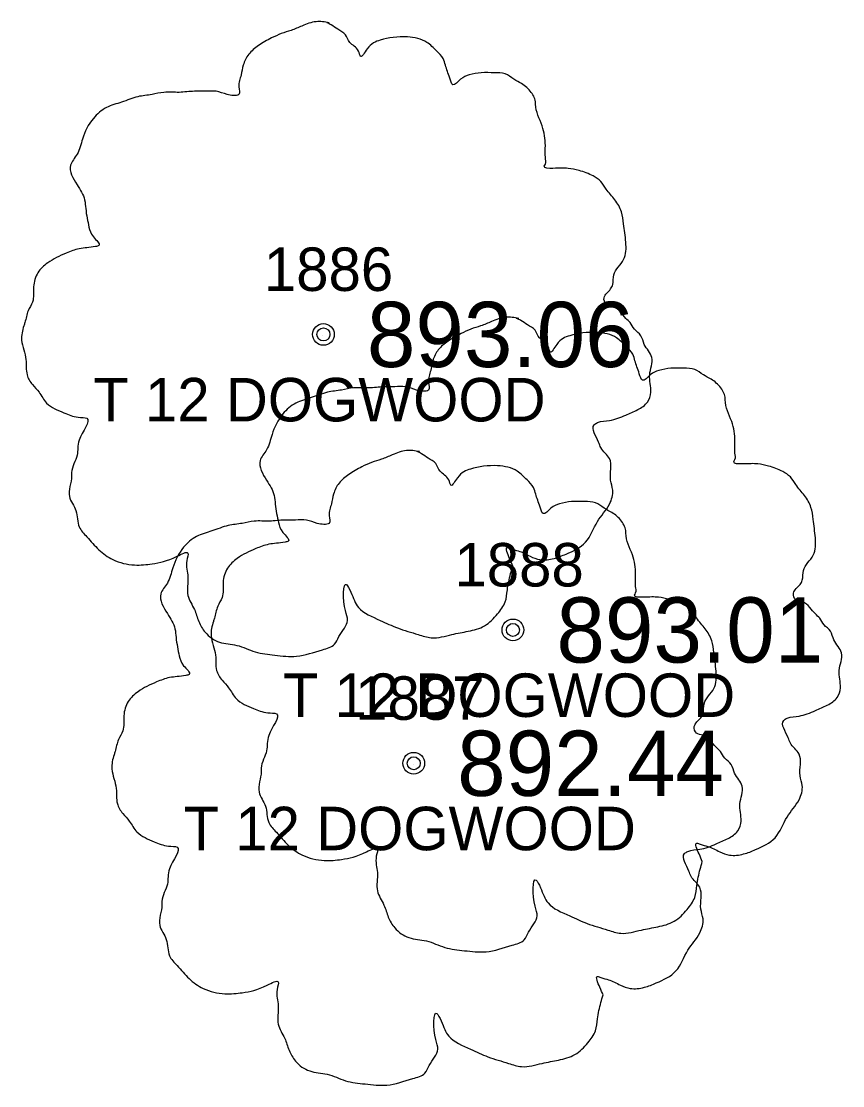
# Model space of a CAD drawing. Extents: x 1448136 to 1453623, y 1125056 to 1128842.
# Drawn here: x 1449655.54 to 1449674.44, y 1126828.42 to 1126852.9 of the extents above; entities that cross this region are included whole.
import ezdxf

# ---------------------------------------------------------------- set-up
doc = ezdxf.new("R2010")
doc.units = 0
for name, color, linetype in [('RD_EX_TX_VEG_ELEV', 7, 'Continuous'), ('RD_EX_VEG', 7, 'Continuous'), ('RD_EX_VEG_txCode', 7, 'Continuous'), ('RD_SMD_Locator', 7, 'Continuous')]:
    doc.layers.add(name, color=color, linetype=linetype)

msp = doc.modelspace()

# ---------------------------------------------------------------- linework, layer by layer
at = {"layer": 'RD_EX_VEG'}
for centre, radius in [((1449662.493, 1126845.694), 0.25), ((1449662.48, 1126845.675), 0.0001), ((1449666.852, 1126838.897), 0.25), ((1449666.839, 1126838.878), 0.0001), ((1449664.569, 1126835.831), 0.25), ((1449664.557, 1126835.812), 0.0001)]:
    msp.add_circle(centre, radius, dxfattribs=at)
for points in [[(1449662.625, 1126852.862), (1449662.325, 1126852.887), (1449662, 1126852.787), (1449661.75, 1126852.687), (1449661.525, 1126852.612), (1449661.3, 1126852.512), (1449661, 1126852.337), (1449660.775, 1126852.137), (1449660.65, 1126851.887), (1449660.6, 1126851.662), (1449660.551, 1126851.387), (1449660.551, 1126851.212), (1449660.426, 1126851.187), (1449660.276, 1126851.212), (1449660.026, 1126851.287), (1449659.776, 1126851.287), (1449659.526, 1126851.287), (1449659.176, 1126851.262), (1449658.826, 1126851.262), (1449658.551, 1126851.212), (1449658.227, 1126851.162), (1449657.852, 1126851.037), (1449657.502, 1126850.912), (1449657.202, 1126850.662), (1449656.952, 1126850.188), (1449656.827, 1126849.838), (1449656.677, 1126849.588), (1449656.827, 1126849.138), (1449657.002, 1126848.788), (1449657.027, 1126848.588), (1449657.102, 1126848.164), (1449657.202, 1126847.939), (1449657.327, 1126847.739), (1449657.252, 1126847.714), (1449656.877, 1126847.664), (1449656.577, 1126847.564), (1449656.152, 1126847.339), (1449655.928, 1126847.114), (1449655.828, 1126846.789), (1449655.803, 1126846.439), (1449655.703, 1126846.239), (1449655.628, 1126845.965), (1449655.603, 1126845.89), (1449655.553, 1126845.565), (1449655.653, 1126845.115), (1449655.678, 1126844.765), (1449655.803, 1126844.54), (1449655.953, 1126844.365), (1449656.127, 1126844.115), (1449656.527, 1126843.89), (1449656.852, 1126843.79), (1449657.052, 1126843.766), (1449656.877, 1126843.266), (1449656.827, 1126842.916), (1449656.702, 1126842.516), (1449656.702, 1126842.441), (1449656.652, 1126841.966), (1449656.802, 1126841.641), (1449656.877, 1126841.267), (1449657.052, 1126841.042), (1449657.327, 1126840.742), (1449657.652, 1126840.517), (1449658.152, 1126840.392), (1449658.551, 1126840.417), (1449659.126, 1126840.592), (1449659.376, 1126840.667), (1449659.351, 1126840.492), (1449659.376, 1126840.117), (1449659.376, 1126839.692), (1449659.526, 1126839.367), (1449659.626, 1126839.093), (1449659.776, 1126838.843), (1449660.101, 1126838.618), (1449660.501, 1126838.543), (1449660.925, 1126838.393), (1449661.375, 1126838.318), (1449661.875, 1126838.293), (1449662.475, 1126838.443), (1449662.75, 1126838.568), (1449662.85, 1126838.743), (1449663.049, 1126839.118), (1449662.999, 1126839.342), (1449663.024, 1126839.942), (1449663.124, 1126839.767), (1449663.299, 1126839.417), (1449663.799, 1126839.118), (1449664.199, 1126838.943), (1449664.674, 1126838.793), (1449664.974, 1126838.718), (1449665.448, 1126838.793), (1449665.823, 1126838.868), (1449666.198, 1126838.993), (1449666.498, 1126839.267), (1449666.673, 1126839.542), (1449666.723, 1126839.817), (1449666.798, 1126840.192), (1449666.848, 1126840.367)], [(1449666.848, 1126840.367), (1449666.773, 1126840.542), (1449666.723, 1126840.792), (1449666.798, 1126840.767), (1449666.973, 1126840.717), (1449667.248, 1126840.592), (1449667.473, 1126840.517), (1449667.797, 1126840.542), (1449668.072, 1126840.642), (1449668.522, 1126840.917), (1449668.797, 1126841.392), (1449669.072, 1126841.791), (1449669.147, 1126842.116), (1449669.097, 1126842.341), (1449669.072, 1126842.841), (1449668.872, 1126843.091), (1449668.822, 1126843.216), (1449668.722, 1126843.616), (1449668.797, 1126843.666), (1449669.072, 1126843.716), (1449669.447, 1126843.84), (1449669.722, 1126843.965), (1449669.946, 1126844.14), (1449670.021, 1126844.365), (1449669.996, 1126844.765), (1449670.046, 1126845.165), (1449669.971, 1126845.315), (1449669.871, 1126845.465), (1449669.796, 1126845.665), (1449669.647, 1126845.815), (1449669.547, 1126845.965), (1449669.447, 1126846.064), (1449669.322, 1126846.214), (1449669.147, 1126846.339), (1449668.997, 1126846.389), (1449668.947, 1126846.539), (1449669.097, 1126846.739), (1449669.147, 1126846.839), (1449669.172, 1126847.064), (1449669.397, 1126847.414), (1449669.447, 1126847.814), (1449669.397, 1126848.239), (1449669.347, 1126848.513), (1449669.197, 1126848.788), (1449668.997, 1126849.038), (1449668.872, 1126849.213), (1449668.697, 1126849.338), (1449668.372, 1126849.463), (1449668.122, 1126849.513), (1449667.772, 1126849.513), (1449667.572, 1126849.563), (1449667.597, 1126849.613), (1449667.597, 1126849.763), (1449667.597, 1126850.038), (1449667.522, 1126850.488), (1449667.373, 1126850.987), (1449667.373, 1126851.012), (1449667.273, 1126851.262), (1449667.048, 1126851.462), (1449666.873, 1126851.562), (1449666.673, 1126851.687), (1449666.423, 1126851.712), (1449666.123, 1126851.712), (1449665.848, 1126851.662), (1449665.648, 1126851.562), (1449665.473, 1126851.437), (1449665.398, 1126851.587), (1449665.298, 1126851.887), (1449665.248, 1126852.037), (1449665.099, 1126852.212), (1449664.874, 1126852.412), (1449664.424, 1126852.537), (1449663.799, 1126852.462), (1449663.499, 1126852.262), (1449663.349, 1126852.087), (1449663.299, 1126852.212), (1449663.099, 1126852.412), (1449662.999, 1126852.587), (1449662.825, 1126852.712), (1449662.675, 1126852.812), (1449662.575, 1126852.862)], [(1449666.984, 1126846.064), (1449666.684, 1126846.089), (1449666.359, 1126845.989), (1449666.109, 1126845.89), (1449665.884, 1126845.815), (1449665.66, 1126845.715), (1449665.36, 1126845.54), (1449665.135, 1126845.34), (1449665.01, 1126845.09), (1449664.96, 1126844.865), (1449664.91, 1126844.59), (1449664.91, 1126844.415), (1449664.785, 1126844.39), (1449664.635, 1126844.415), (1449664.385, 1126844.49), (1449664.135, 1126844.49), (1449663.885, 1126844.49), (1449663.535, 1126844.465), (1449663.186, 1126844.465), (1449662.911, 1126844.415), (1449662.586, 1126844.365), (1449662.211, 1126844.24), (1449661.861, 1126844.115), (1449661.561, 1126843.865), (1449661.311, 1126843.391), (1449661.186, 1126843.041), (1449661.037, 1126842.791), (1449661.186, 1126842.341), (1449661.361, 1126841.991), (1449661.386, 1126841.791), (1449661.461, 1126841.367), (1449661.561, 1126841.142), (1449661.686, 1126840.942), (1449661.611, 1126840.917), (1449661.236, 1126840.867), (1449660.937, 1126840.767), (1449660.512, 1126840.542), (1449660.287, 1126840.317), (1449660.187, 1126839.992), (1449660.162, 1126839.642), (1449660.062, 1126839.442), (1449659.987, 1126839.167), (1449659.962, 1126839.092), (1449659.912, 1126838.768), (1449660.012, 1126838.318), (1449660.037, 1126837.968), (1449660.162, 1126837.743), (1449660.312, 1126837.568), (1449660.487, 1126837.318), (1449660.887, 1126837.093), (1449661.211, 1126836.993), (1449661.411, 1126836.968), (1449661.236, 1126836.469), (1449661.186, 1126836.119), (1449661.062, 1126835.719), (1449661.062, 1126835.644), (1449661.012, 1126835.169), (1449661.161, 1126834.844), (1449661.236, 1126834.47), (1449661.411, 1126834.245), (1449661.686, 1126833.945), (1449662.011, 1126833.72), (1449662.511, 1126833.595), (1449662.911, 1126833.62), (1449663.486, 1126833.795), (1449663.735, 1126833.87), (1449663.71, 1126833.695), (1449663.735, 1126833.32), (1449663.735, 1126832.895), (1449663.885, 1126832.57), (1449663.985, 1126832.295), (1449664.135, 1126832.046), (1449664.46, 1126831.821), (1449664.86, 1126831.746), (1449665.285, 1126831.596), (1449665.735, 1126831.521), (1449666.234, 1126831.496), (1449666.834, 1126831.646), (1449667.109, 1126831.771), (1449667.209, 1126831.946), (1449667.409, 1126832.32), (1449667.359, 1126832.545), (1449667.384, 1126833.145), (1449667.484, 1126832.97), (1449667.659, 1126832.62), (1449668.158, 1126832.32), (1449668.558, 1126832.146), (1449669.033, 1126831.996), (1449669.333, 1126831.921), (1449669.808, 1126831.996), (1449670.183, 1126832.071), (1449670.557, 1126832.196), (1449670.857, 1126832.47), (1449671.032, 1126832.745), (1449671.082, 1126833.02), (1449671.157, 1126833.395), (1449671.207, 1126833.57)], [(1449671.207, 1126833.57), (1449671.132, 1126833.745), (1449671.082, 1126833.995), (1449671.157, 1126833.97), (1449671.332, 1126833.92), (1449671.607, 1126833.795), (1449671.832, 1126833.72), (1449672.157, 1126833.745), (1449672.432, 1126833.845), (1449672.881, 1126834.12), (1449673.156, 1126834.594), (1449673.431, 1126834.994), (1449673.506, 1126835.319), (1449673.456, 1126835.544), (1449673.431, 1126836.044), (1449673.231, 1126836.294), (1449673.181, 1126836.419), (1449673.081, 1126836.818), (1449673.156, 1126836.868), (1449673.431, 1126836.918), (1449673.806, 1126837.043), (1449674.081, 1126837.168), (1449674.306, 1126837.343), (1449674.381, 1126837.568), (1449674.356, 1126837.968), (1449674.406, 1126838.368), (1449674.331, 1126838.518), (1449674.231, 1126838.668), (1449674.156, 1126838.868), (1449674.006, 1126839.017), (1449673.906, 1126839.167), (1449673.806, 1126839.267), (1449673.681, 1126839.417), (1449673.506, 1126839.542), (1449673.356, 1126839.592), (1449673.306, 1126839.742), (1449673.456, 1126839.942), (1449673.506, 1126840.042), (1449673.531, 1126840.267), (1449673.756, 1126840.617), (1449673.806, 1126841.017), (1449673.756, 1126841.441), (1449673.706, 1126841.716), (1449673.556, 1126841.991), (1449673.356, 1126842.241), (1449673.231, 1126842.416), (1449673.056, 1126842.541), (1449672.731, 1126842.666), (1449672.482, 1126842.716), (1449672.132, 1126842.716), (1449671.932, 1126842.766), (1449671.957, 1126842.816), (1449671.957, 1126842.966), (1449671.957, 1126843.241), (1449671.882, 1126843.69), (1449671.732, 1126844.19), (1449671.732, 1126844.215), (1449671.632, 1126844.465), (1449671.407, 1126844.665), (1449671.232, 1126844.765), (1449671.032, 1126844.89), (1449670.782, 1126844.915), (1449670.482, 1126844.915), (1449670.208, 1126844.865), (1449670.008, 1126844.765), (1449669.833, 1126844.64), (1449669.758, 1126844.79), (1449669.658, 1126845.09), (1449669.608, 1126845.24), (1449669.458, 1126845.415), (1449669.233, 1126845.615), (1449668.783, 1126845.74), (1449668.158, 1126845.665), (1449667.859, 1126845.465), (1449667.709, 1126845.29), (1449667.659, 1126845.415), (1449667.459, 1126845.615), (1449667.359, 1126845.79), (1449667.184, 1126845.915), (1449667.034, 1126846.014), (1449666.934, 1126846.064)], [(1449664.701, 1126842.999), (1449664.401, 1126843.024), (1449664.077, 1126842.924), (1449663.827, 1126842.824), (1449663.602, 1126842.749), (1449663.377, 1126842.649), (1449663.077, 1126842.474), (1449662.852, 1126842.274), (1449662.727, 1126842.024), (1449662.677, 1126841.799), (1449662.627, 1126841.524), (1449662.627, 1126841.349), (1449662.502, 1126841.324), (1449662.352, 1126841.349), (1449662.102, 1126841.424), (1449661.852, 1126841.424), (1449661.603, 1126841.424), (1449661.253, 1126841.399), (1449660.903, 1126841.399), (1449660.628, 1126841.349), (1449660.303, 1126841.299), (1449659.928, 1126841.174), (1449659.578, 1126841.049), (1449659.279, 1126840.799), (1449659.029, 1126840.325), (1449658.904, 1126839.975), (1449658.754, 1126839.725), (1449658.904, 1126839.275), (1449659.079, 1126838.925), (1449659.104, 1126838.725), (1449659.179, 1126838.301), (1449659.279, 1126838.076), (1449659.404, 1126837.876), (1449659.329, 1126837.851), (1449658.954, 1126837.801), (1449658.654, 1126837.701), (1449658.229, 1126837.476), (1449658.004, 1126837.251), (1449657.904, 1126836.926), (1449657.879, 1126836.576), (1449657.779, 1126836.376), (1449657.704, 1126836.102), (1449657.679, 1126836.027), (1449657.629, 1126835.702), (1449657.729, 1126835.252), (1449657.754, 1126834.902), (1449657.879, 1126834.677), (1449658.029, 1126834.502), (1449658.204, 1126834.252), (1449658.604, 1126834.027), (1449658.929, 1126833.927), (1449659.129, 1126833.903), (1449658.954, 1126833.403), (1449658.904, 1126833.053), (1449658.779, 1126832.653), (1449658.779, 1126832.578), (1449658.729, 1126832.103), (1449658.879, 1126831.778), (1449658.954, 1126831.404), (1449659.129, 1126831.179), (1449659.404, 1126830.879), (1449659.728, 1126830.654), (1449660.228, 1126830.529), (1449660.628, 1126830.554), (1449661.203, 1126830.729), (1449661.453, 1126830.804), (1449661.428, 1126830.629), (1449661.453, 1126830.254), (1449661.453, 1126829.829), (1449661.603, 1126829.504), (1449661.703, 1126829.23), (1449661.852, 1126828.98), (1449662.177, 1126828.755), (1449662.577, 1126828.68), (1449663.002, 1126828.53), (1449663.452, 1126828.455), (1449663.952, 1126828.43), (1449664.551, 1126828.58), (1449664.826, 1126828.705), (1449664.926, 1126828.88), (1449665.126, 1126829.255), (1449665.076, 1126829.479), (1449665.101, 1126830.079), (1449665.201, 1126829.904), (1449665.376, 1126829.554), (1449665.876, 1126829.255), (1449666.276, 1126829.08), (1449666.75, 1126828.93), (1449667.05, 1126828.855), (1449667.525, 1126828.93), (1449667.9, 1126829.005), (1449668.275, 1126829.13), (1449668.575, 1126829.404), (1449668.749, 1126829.679), (1449668.799, 1126829.954), (1449668.874, 1126830.329), (1449668.924, 1126830.504)], [(1449668.924, 1126830.504), (1449668.849, 1126830.679), (1449668.799, 1126830.929), (1449668.874, 1126830.904), (1449669.049, 1126830.854), (1449669.324, 1126830.729), (1449669.549, 1126830.654), (1449669.874, 1126830.679), (1449670.149, 1126830.779), (1449670.599, 1126831.054), (1449670.874, 1126831.529), (1449671.148, 1126831.928), (1449671.223, 1126832.253), (1449671.173, 1126832.478), (1449671.148, 1126832.978), (1449670.948, 1126833.228), (1449670.898, 1126833.353), (1449670.799, 1126833.753), (1449670.874, 1126833.803), (1449671.148, 1126833.853), (1449671.523, 1126833.977), (1449671.798, 1126834.102), (1449672.023, 1126834.277), (1449672.098, 1126834.502), (1449672.073, 1126834.902), (1449672.123, 1126835.302), (1449672.048, 1126835.452), (1449671.948, 1126835.602), (1449671.873, 1126835.802), (1449671.723, 1126835.952), (1449671.623, 1126836.102), (1449671.523, 1126836.201), (1449671.398, 1126836.351), (1449671.223, 1126836.476), (1449671.073, 1126836.526), (1449671.023, 1126836.676), (1449671.173, 1126836.876), (1449671.223, 1126836.976), (1449671.248, 1126837.201), (1449671.473, 1126837.551), (1449671.523, 1126837.951), (1449671.473, 1126838.376), (1449671.423, 1126838.65), (1449671.273, 1126838.925), (1449671.073, 1126839.175), (1449670.948, 1126839.35), (1449670.774, 1126839.475), (1449670.449, 1126839.6), (1449670.199, 1126839.65), (1449669.849, 1126839.65), (1449669.649, 1126839.7), (1449669.674, 1126839.75), (1449669.674, 1126839.9), (1449669.674, 1126840.175), (1449669.599, 1126840.625), (1449669.449, 1126841.124), (1449669.449, 1126841.149), (1449669.349, 1126841.399), (1449669.124, 1126841.599), (1449668.949, 1126841.699), (1449668.749, 1126841.824), (1449668.5, 1126841.849), (1449668.2, 1126841.849), (1449667.925, 1126841.799), (1449667.725, 1126841.699), (1449667.55, 1126841.574), (1449667.475, 1126841.724), (1449667.375, 1126842.024), (1449667.325, 1126842.174), (1449667.175, 1126842.349), (1449666.95, 1126842.549), (1449666.5, 1126842.674), (1449665.876, 1126842.599), (1449665.576, 1126842.399), (1449665.426, 1126842.224), (1449665.376, 1126842.349), (1449665.176, 1126842.549), (1449665.076, 1126842.724), (1449664.901, 1126842.849), (1449664.751, 1126842.949), (1449664.651, 1126842.999)]]:
    msp.add_spline(points, degree=3, dxfattribs=at)
at = {"layer": 'RD_SMD_Locator'}
for centre in [(1449662.493, 1126845.694), (1449666.852, 1126838.897), (1449664.569, 1126835.831)]:
    msp.add_circle(centre, 0.15, dxfattribs=at)

# ---------------------------------------------------------------- texts
at = {"layer": 'RD_EX_TX_VEG_ELEV'}
for s, p in [('893.06', (1449663.493, 1126844.944)), ('893.01', (1449667.852, 1126838.147)), ('892.44', (1449665.569, 1126835.081))]:
    msp.add_text(s, height=1.5, dxfattribs=at).set_placement(p)
at = {"layer": 'RD_EX_VEG_txCode'}
for s, p in [('1886', (1449661.123, 1126846.694)), ('T 12 DOGWOOD', (1449657.201, 1126843.694)), ('1888', (1449665.506, 1126839.897)), ('T 12 DOGWOOD', (1449661.561, 1126836.897)), ('1887', (1449663.223, 1126836.831)), ('T 12 DOGWOOD', (1449659.278, 1126833.831))]:
    msp.add_text(s, height=1, dxfattribs=at).set_placement(p)

doc.saveas('drawing.dxf')
